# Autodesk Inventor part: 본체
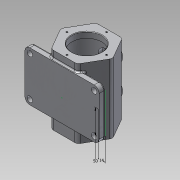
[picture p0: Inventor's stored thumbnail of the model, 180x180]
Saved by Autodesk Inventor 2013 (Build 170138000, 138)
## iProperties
Created: 2021-06
Part Number: 본체
Material: 알루미늄 6061
Document SubType Name: Modeling
Designer: cad21
Density: 2.71 g/cm^3
Mass: 1501.03 g
Surface Area: 1102.04 cm^2
Volume: 553.886 cm^3
Author: cad21
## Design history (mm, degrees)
sketch "스케치1"
  geometry: L1 (-26.25, -45.466)-(-52.5, 0); L2 (-52.5, 0)-(-26.25, 45.466); L3 (-26.25, 45.466)-(26.25, 45.466); L4 (26.25, 45.466)-(52.5, 0); L5 (52.5, 0)-(26.25, -45.466); L6 (26.25, -45.466)-(-26.25, -45.466); L7 (-73.5, 0)-(73.5, 0) reference; L8 (0, -63.653)-(0, 63.653) reference; 1 further point
  constraints: 12 end point, 1 parallel, 13 other
  dimensions: "d0" = 105 distance of L4.end L1.end
extrude "돌출1" new body sketch "스케치1" stored distance "d2" = 140; taper "d3" = 0 deg
sketch "스케치13"
  geometry: L1 (73.5, 0)-(-73.5, 0) reference; L2 (0, -98)-(0, 98) reference; L3 (52.5, 70)-(26.25, 70) reference; L4 (-26.25, -70)-(26.25, -70) reference; C1 r 20 at (0, -30); C2 r 20 at (0, 30); 1 further point
  constraints: 2 centre point, 2 point on line
  dimensions: "d60" = 40 diameter of C1; "d65" = 40 distance from line of L4 C1.centre; "d66" = 40 diameter of C2; "d67" = 60 distance of C1.centre C2.centre
extrude "돌출10" join sketch "스케치13" distance "d63" = 52.5; taper "d64" = 0 deg
node "작업 평면1"
sketch "스케치20"
  geometry: 1 further point
sketch "스케치14"
  geometry: C1 r 20 at (0, 0) reference; C2 r 12.5 at (0, 0); C3 r 12.5 at (0, -60); 1 further point
  constraints: 2 centre point, 1 coincident
  dimensions: "d68" = 25 diameter of C2; "d69" = 25 diameter of C3; "d70" = 60 distance of C3.centre C2.centre
extrude "돌출11" cut sketch "스케치14" distance "d71" = 30; taper "d72" = 0 deg
sketch "스케치15"
  geometry: L1 (-73.5, -30)-(73.5, -30) reference; L2 (0, 68)-(0, -128) reference; C1 r 20 at (0, 0) reference; C2 r 15 at (0, 0); C3 r 15 at (0, -60); 1 further point
  constraints: 2 centre point, 1 coincident, 1 point on line
  dimensions: "d73" = 30 diameter of C2; "d74" = 30 diameter of C3; "d75" = 60 distance of C1.centre C3.centre
extrude "돌출12" cut sketch "스케치15" distance "d76" = 8; taper "d77" = 0 deg
sketch "스케치9"
  geometry: C1 r 30 at (0, 0) reference; C2 r 37.5 at (0, 0)
  constraints: 1 centre point, 1 coincident
  dimensions: "d30" = 75 diameter of C2
extrude "돌출8" cut sketch "스케치9" stored distance "d31" = 116; taper "d32" = 0 deg
sketch "스케치10"
  geometry: C1 r 37.5 at (0, 0) reference; C2 r 37.5 at (0, 0); C3 r 30 at (0, 0)
  constraints: 2 centre point, 2 coincident
  dimensions: "d33" = 75 diameter of C2; "d34" = 60 diameter of C3
extrude "돌출9" join sketch "스케치10" distance "d35" = 12; taper "d36" = 0 deg
sketch "스케치16"
  geometry: L1 (69.448, -69.448)-(-63.488, 63.488); L2 (96.036, 0)-(-90.076, 0) reference; L3 (0, -96.932)-(0, 95.458) reference; L4 (-49.171, -49.171)-(67.973, 67.973); C1 r 30 at (0, 0) reference; A1 r 40 centre (0, 0) between (28.284, 28.284) and (28.284, -28.284); 2 further points
  constraints: 6 point on line, 4 end point, 4 point on circle, 1 centre point, 1 coincident, 1 perpendicular
  dimensions: "d79" = 45 deg angle of L3 L1; "d80" = 80 diameter of A1
hole "구멍4" sketch "스케치16" at (28.284, 28.284), (28.284, -28.284), (-28.284, -28.284), (-28.284, 28.284) diameter "d81" = 3.242; stored, may be unused: countersink angle "d85" = 90 deg, drill point angle "d87" = 118 deg; dims "d82" = 8, "d83" = 4, "d84" = 2, "d86" = 10
sketch "스케치17"
  geometry: L1 (-73.5, 0)-(73.5, 0) reference; L2 (0, -70.5)-(0, 73) reference; C1 r 30 at (0, 0) reference; A1 r 40 centre (0, 0) between (0, 40) and (-40, 0); 2 further points
  constraints: 4 point on circle, 4 point on line, 1 centre point, 1 coincident
  dimensions: "d88" = 80 diameter of A1
hole "구멍5" sketch "스케치17" at (0, 40), (-40, 0), (40, 0), (0, -40) diameter "d89" = 3.242; stored, may be unused: countersink angle "d93" = 90 deg, drill point angle "d95" = 118 deg; dims "d90" = 8, "d91" = 4, "d92" = 2, "d94" = 10
fillet "모깎기2" dims "d101" = 3, "d102" = 5
sketch "스케치21"
  geometry: L1 (-75, -45)-(75, -45); L2 (75, -45)-(75, 55); L3 (75, 55)-(-75, 55); L4 (-75, 55)-(-75, -45); L5 (147.061, 0)-(-84.316, 0) reference; L6 (0, -98)-(0, 98) reference; L7 (-26.25, -70)-(26.25, -70) reference; 3 further points
  constraints: 8 end point, 2 parallel, 1 horizontal, 1 perpendicular, 1 other
  dimensions: "d111" = 150 distance of L1.start L1.end; "d113" = 100 distance of L3.end L1.start; "d114" = 25 distance between parallel lines of L7 L1
extrude "돌출14" join sketch "스케치21" distance "d115" = 12; taper "d116" = 0 deg
chamfer "모따기1" distance "d103" = 1; stored, may be unused: second distance "d104" = 2, angle "d105" = 45 deg
fillet "모깎기3" dims "d117" = 8, "d118" = 3, "d119" = 10
sketch "스케치22"
  geometry: C1 r 5.5 at (-65, 35); C2 r 5.5 at (-65, -45); A1 r 7 centre (-65, 35) between (-65, 42) and (-72, 35) reference; A2 r 7 centre (-65, -45) between (-72, -45) and (-65, -52) reference; 1 further point
  constraints: 2 centre point, 2 coincident
  dimensions: "d120" = 11 diameter of C1; "d121" = 11 diameter of C2
extrude "돌출15" cut sketch "스케치22" distance "d122" = 12; taper "d123" = 0 deg
sketch "스케치23"
  geometry: L1 (35.757, 42)-(65, 42) reference; L2 (35.757, -52)-(35.757, 42) reference; L3 (65, -52)-(35.757, -52) reference; L4 (72, 35)-(72, -45) reference; L5 (75, -45)-(75, 35) reference; L6 (65, 45)-(32.293, 45) reference; C1 r 5.5 at (65, 35) reference; C2 r 5.5 at (65, -45) reference; A1 r 7 centre (65, 35) between (72, 35) and (65, 42) reference; A2 r 7 centre (65, -45) between (65, -52) and (72, -45) reference; 2 further points
  constraints: 1 other
  dimensions: "d124" = 14 distance from line of point (61, -5) L5; "d125" = 50 distance from line of L6 point (61, -5)
node "솔리드1"
mirror "대칭3"
mirror "대칭5"
